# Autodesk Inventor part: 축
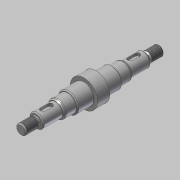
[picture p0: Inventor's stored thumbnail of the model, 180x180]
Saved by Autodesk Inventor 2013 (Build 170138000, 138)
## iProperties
Created: 2019-09
Part Number: 축
Material: 강철, 연강
Document SubType Name: Modeling
Designer: mduedu
Density: 7.86 g/cm^3
Mass: 210.278 g
Surface Area: 69.4769 cm^2
Volume: 26.7529 cm^3
Author: mduedu
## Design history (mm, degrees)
sketch "스케치1"
  geometry: L1 (0, 0)-(15, 0); L2 (15, 0)-(15, 5); L3 (15, 5)-(0, 5); L4 (0, 5)-(0, 0); L5 (15, 0)-(34, 0); L6 (34, 0)-(34, 7); L7 (34, 7)-(15, 7); L8 (15, 7)-(15, 0); L9 (34, 0)-(46, 0); L10 (46, 0)-(46, 8.5); L11 (46, 8.5)-(34, 8.5); L12 (34, 8.5)-(34, 0); L13 (46, 0)-(62, 0); L14 (62, 10)-(46, 10); L15 (46, 10)-(46, 0); L16 (62, 10)-(62, 0); L17 (62, 0)-(68, 0); L18 (68, 0)-(68, 13.5); L19 (68, 13.5)-(62, 13.5); L20 (62, 13.5)-(62, 0)
  constraints: 40 end point, 10 parallel, 5 horizontal, 4 perpendicular, 1 vertical
  dimensions: "d2" = 15 distance of L2.end L3.end; "d3" = 19 distance of L6.end L7.end; "d8" = 16 distance of L14.start L14.end; "d9" = 10 diameter of L3 L1; "d10" = 14 diameter of L7 L5; "d11" = 17 diameter of L11 L9; "d12" = 20 diameter of L14 L13; "d73" = 12 distance of L10.end L11.end (derived); "d74" = 27 diameter of L19 L17; "d75" = 6 distance of L18.end L19.end; "d76" = 68 distance between parallel lines of L4 L18
revolve "회전1" sketch "스케치1" stored, may be unused: angle "d17" = 90 deg
revolve "회전2" stored, may be unused: angle "d22" = 90 deg
fillet "모깎기1" dims "d23" = 0.6
feature "스레드1" dims "d24" = 10, "d25" = 0
chamfer "모따기1" distance "d26" = 1; stored, may be unused: second distance "d27" = 2, angle "d28" = 45 deg
chamfer "모따기2" distance "d29" = 1; stored, may be unused: second distance "d30" = 2, angle "d31" = 45 deg
chamfer "모따기3" distance "d32" = 1.819; stored, may be unused: second distance "d33" = 2, angle "d34" = 30 deg
fillet "모깎기2" dims "d35" = 2
chamfer "모따기4" distance "d36" = 1; stored, may be unused: second distance "d37" = 2, angle "d38" = 30 deg
fillet "모깎기3" dims "d39" = 0.3
node "작업 평면1"
sketch "스케치3" dims "d51" = 12
  geometry: L1 (3, -2.5)-(-4, -2.5); L2 (-4, -2.5)-(-4, 2.5); L3 (-4, 2.5)-(3, 2.5); L4 (3, 2.5)-(3, -2.5); L5 (-9.5, 7.45)-(-9.5, -7.45) reference; 3 further points
  constraints: 8 end point, 2 midpoint, 2 parallel, 2 vertical alignment, 1 horizontal, 1 horizontal alignment, 1 perpendicular, 4 other
  dimensions: "d50" = 3 dimension on L5; "d52" = 5 distance between parallel lines of L3 L1
extrude "돌출1" cut sketch "스케치3" distance "d53" = 3; taper "d54" = 0 deg
node "솔리드1"
mirror "대칭1"
sketch "스케치2"
  geometry: L1 (0, -5)-(0, 5) reference; L2 (0, 5)-(15, 5) reference; L3 (15, 5)-(15, 7) reference; L4 (15, 7)-(34, 7) reference; L5 (34, 7)-(34, 8.5) reference; L6 (34, 8.5)-(46, 8.5) reference; L7 (46, 8.5)-(46, 10) reference; L8 (46, 10)-(62, 10) reference; L9 (62, -10)-(46, -10) reference; L10 (46, -10)-(46, -8.5) reference; L11 (46, -8.5)-(34, -8.5) reference; L12 (34, -8.5)-(34, -7) reference; L13 (34, -7)-(15, -7) reference; L14 (15, -7)-(15, -5) reference; L15 (15, -5)-(0, -5) reference; L16 (0, 0)-(74, 0); L17 (15, 5)-(12.014, 5); L18 (13.4, 4.2)-(15, 4.2); L19 (15, 4.2)-(15, 5); L20 (12.014, 5)-(13.4, 4.2); L21 (62, 10)-(62, 13.5) reference; L22 (62, 13.5)-(68, 13.5) reference; L23 (68, 13.5)-(68, -13.5) reference; L24 (68, -13.5)-(62, -13.5) reference; L25 (62, -13.5)-(62, -10) reference
  constraints: 10 end point, 1 horizontal, 1 parallel, 1 vertical
  dimensions: "d18" = 30 deg angle of L2 L20; "d19" = 8.4 diameter of L18 L16; "d21" = 2.986 distance from line of L17.end L19
node "절단 모서리 투영1"
